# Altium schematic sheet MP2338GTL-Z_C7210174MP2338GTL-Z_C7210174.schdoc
size 127 x 101 mm
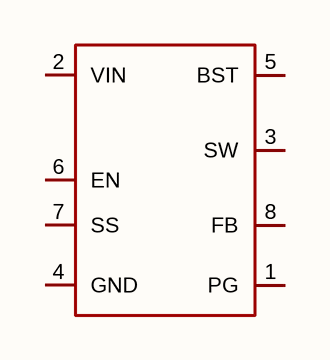
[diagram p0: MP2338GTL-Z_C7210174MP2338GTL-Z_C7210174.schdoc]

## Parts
U?  mp2338gtl-z_c7210174  [SOT-583-8_L2.1-W1.2-P0.50-LS1.6-BR]  (value not drawn)

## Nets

Not connected (* = marked no-connect by the designer): U? 1(PG) 2(VIN) 3(SW) 4(GND) 5(BST) 6(EN) 7(SS) 8(FB)

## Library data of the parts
U? = mp2338gtl-z_c7210174: 功能类型:降压型;工作电压:4.5V~28V;输出电压:500mV~16V;输出电流:3A;输出类型:可调;; Manufacturer: MPS(芯源); AddInBom: yes; ModelId: 9c4fd216f1c14d02983b26164f06703c; ModelTransform: 62.992,82.86015,0,0,0,0,0,0,0; Function: 降压型; Output Current: 3A; Frequency - Switching: 450kHz; Synchronous Rectifier: 是; Number of Outputs: 1; Topology: 降压式; Quiescent Current: 160uA; Switch tube (built-in/external): 内置; Output Type: 可调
